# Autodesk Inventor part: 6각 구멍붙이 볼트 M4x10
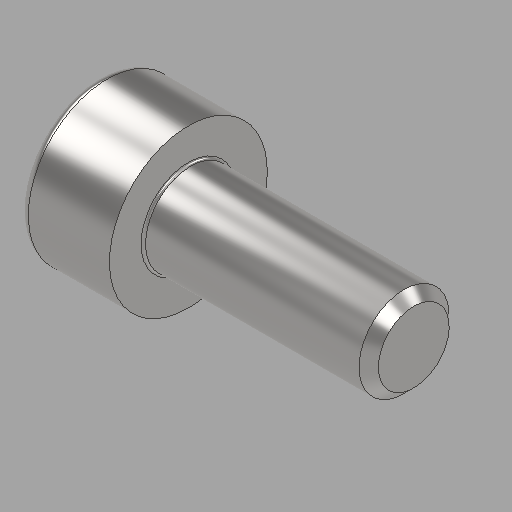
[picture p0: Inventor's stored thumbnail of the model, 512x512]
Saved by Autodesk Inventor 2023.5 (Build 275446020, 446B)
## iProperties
Created: 2026-03
Part Number: 6각 구멍붙이 볼트 M4x10
Material: 강철, 연강
Description: 6각머리 태핑 나사
Document SubType Name: Modeling
Designer: mirae
Density: 7.85 g/cm^3
Appearance: 기본값
Author: jhkim
Sending System: Autodesk Inventor 2026
Preprocessor: ST-DEVELOPER v20.1
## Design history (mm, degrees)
node "6각 구멍붙이 볼트 M4x101"
node "솔리드1"
body "Solid1"
